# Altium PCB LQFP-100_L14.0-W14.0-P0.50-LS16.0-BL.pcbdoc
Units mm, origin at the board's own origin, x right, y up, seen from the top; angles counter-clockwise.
Board outline 29.4 x 29.73 mm, 2 copper layers (Top Layer, Bottom Layer), stack 0 mm thick; 1 components, 0 nets, 100 pads, 0 vias.
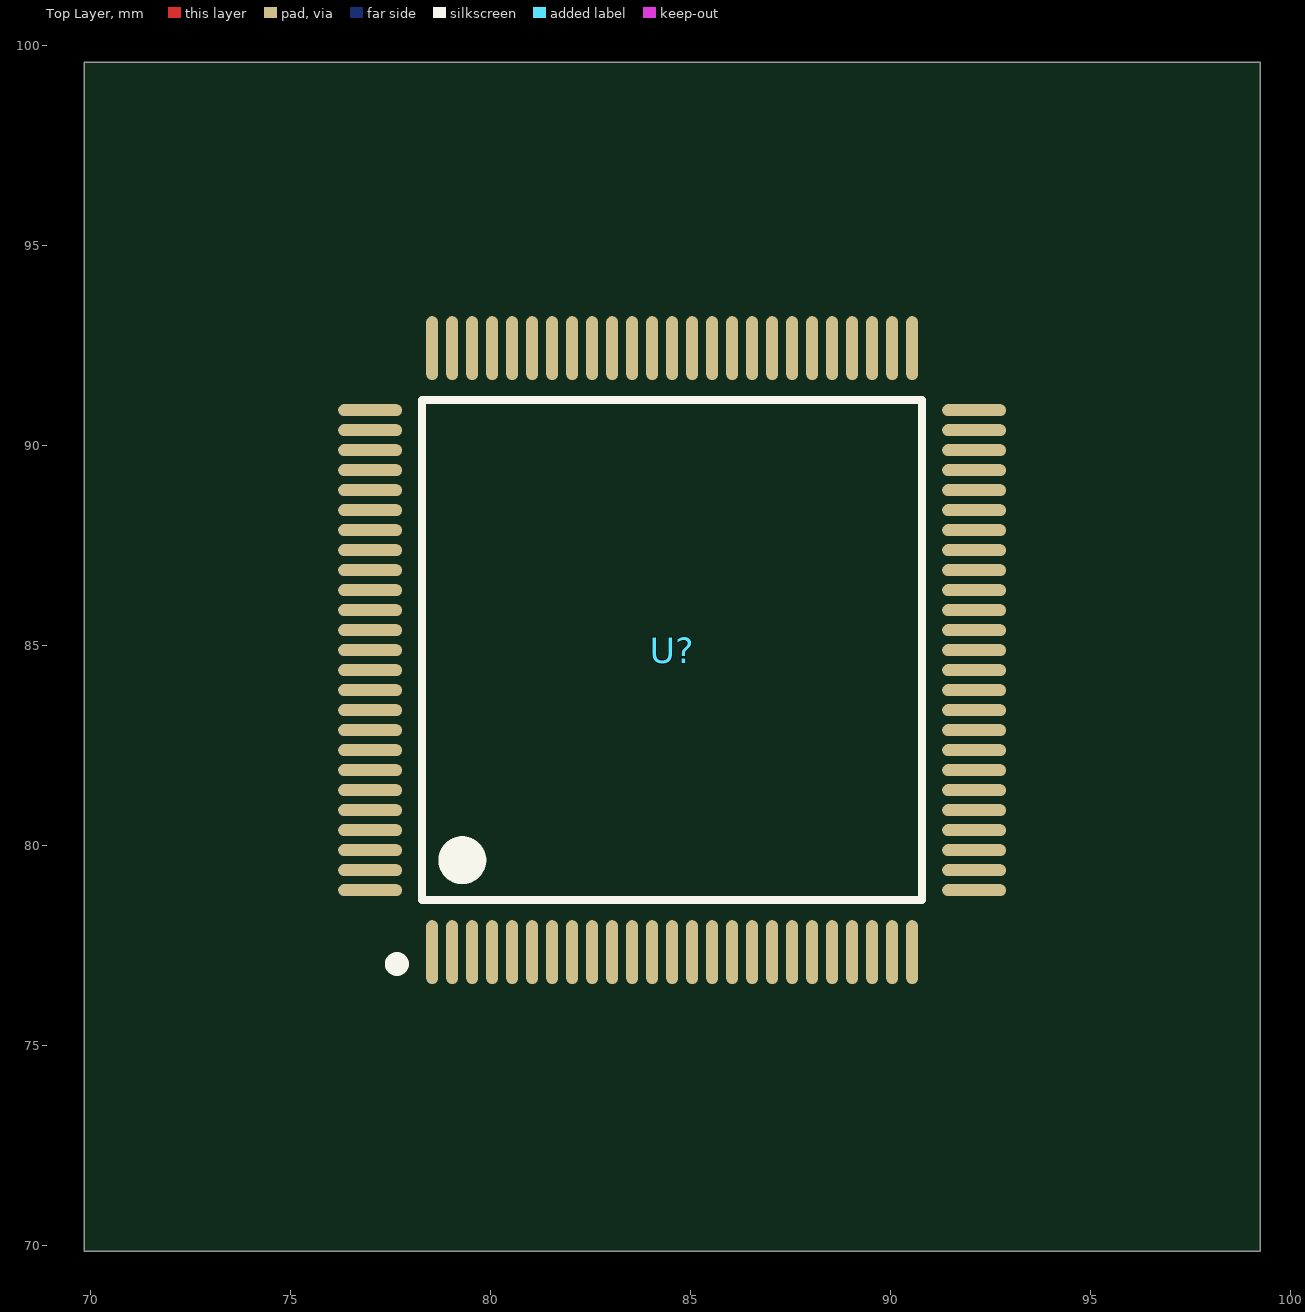
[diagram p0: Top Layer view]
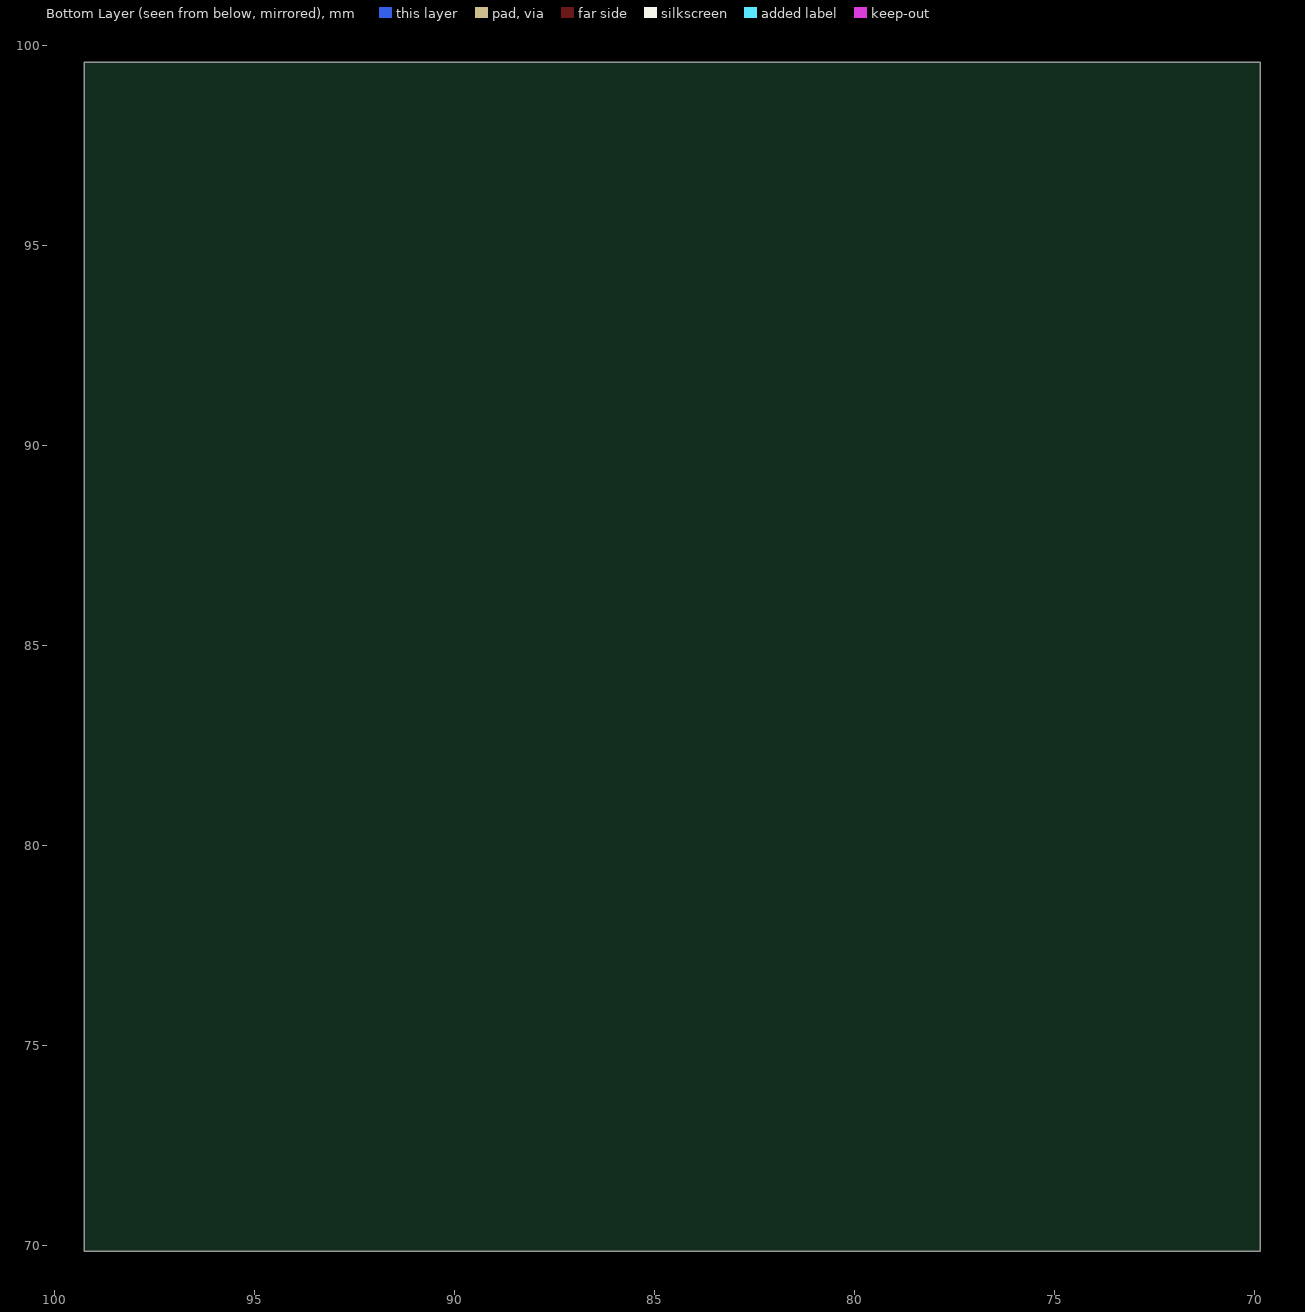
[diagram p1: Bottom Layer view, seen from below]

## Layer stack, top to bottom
Top Layer: signal copper (thickness not stored)
Bottom Layer: signal copper (thickness not stored)

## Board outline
99.25,69.85 69.85,69.85 69.85,99.583 99.25,99.583

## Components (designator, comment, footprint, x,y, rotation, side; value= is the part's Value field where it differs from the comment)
U? "" LQFP-100_L14.0-W14.0-P0.50-LS16.0-BL 84.55,84.883 r0 top

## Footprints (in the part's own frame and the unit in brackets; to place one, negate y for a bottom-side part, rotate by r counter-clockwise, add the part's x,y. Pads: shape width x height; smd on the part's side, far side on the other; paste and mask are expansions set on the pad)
LQFP-100_L14.0-W14.0-P0.50-LS16.0-BL [mm]
  oval 0.3x1.6 smd: 1(-6,-7.55) 2(-5.5,-7.55) 3(-5,-7.55) 4(-4.5,-7.55) 5(-4,-7.55) 6(-3.5,-7.55) 7(-3,-7.55) 8(-2.5,-7.55) 9(-2,-7.55) 10(-1.5,-7.55) 11(-1,-7.55) 12(-0.5,-7.55) 13(0,-7.55) 14(0.5,-7.55) 15(1,-7.55) 16(1.5,-7.55) 17(2,-7.55) 18(2.5,-7.55) 19(3,-7.55) 20(3.5,-7.55) 21(4,-7.55) 22(4.5,-7.55) 23(5,-7.55) 24(5.5,-7.55) 25(6,-7.55) 51(6,7.55) 52(5.5,7.55) 53(5,7.55) 54(4.5,7.55) 55(4,7.55) 56(3.5,7.55) 57(3,7.55) 58(2.5,7.55) 59(2,7.55) 60(1.5,7.55) 61(1,7.55) 62(0.5,7.55) 63(0,7.55) 64(-0.5,7.55) 65(-1,7.55) 66(-1.5,7.55) 67(-2,7.55) 68(-2.5,7.55) 69(-3,7.55) 70(-3.5,7.55) 71(-4,7.55) 72(-4.5,7.55) 73(-5,7.55) 74(-5.5,7.55) 75(-6,7.55)
  oval 1.6x0.3 smd: 26(7.55,-6) 27(7.55,-5.5) 28(7.55,-5) 29(7.55,-4.5) 30(7.55,-4) 31(7.55,-3.5) 32(7.55,-3) 33(7.55,-2.5) 34(7.55,-2) 35(7.55,-1.5) 36(7.55,-1) 37(7.55,-0.5) 38(7.55,0) 39(7.55,0.5) 40(7.55,1) 41(7.55,1.5) 42(7.55,2) 43(7.55,2.5) 44(7.55,3) 45(7.55,3.5) 46(7.55,4) 47(7.55,4.5) 48(7.55,5) 49(7.55,5.5) 50(7.55,6) 76(-7.55,6) 77(-7.55,5.5) 78(-7.55,5) 79(-7.55,4.5) 80(-7.55,4) 81(-7.55,3.5) 82(-7.55,3) 83(-7.55,2.5) 84(-7.55,2) 85(-7.55,1.5) 86(-7.55,1) 87(-7.55,0.5) 88(-7.55,0) 89(-7.55,-0.5) 90(-7.55,-1) 91(-7.55,-1.5) 92(-7.55,-2) 93(-7.55,-2.5) 94(-7.55,-3) 95(-7.55,-3.5) 96(-7.55,-4) 97(-7.55,-4.5) 98(-7.55,-5) 99(-7.55,-5.5) 100(-7.55,-6)
  silkscreen extent -7.03,-8 6.25,6.25

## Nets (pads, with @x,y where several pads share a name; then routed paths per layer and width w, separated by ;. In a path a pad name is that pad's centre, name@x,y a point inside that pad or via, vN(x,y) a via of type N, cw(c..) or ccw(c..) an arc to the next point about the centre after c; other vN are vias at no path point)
pads on no net: U?.1 U?.2 U?.3 U?.4 U?.5 U?.6 U?.7 U?.8 U?.9 U?.10 U?.11 U?.12 U?.13 U?.14 U?.15 U?.16 U?.17 U?.18 U?.19 U?.20 U?.21 U?.22 U?.23 U?.24 U?.25 U?.26 U?.27 U?.28 U?.29 U?.30 U?.31 U?.32 U?.33 U?.34 U?.35 U?.36 U?.37 U?.38 U?.39 U?.40 U?.41 U?.42 U?.43 U?.44 U?.45 U?.46 U?.47 U?.48 U?.49 U?.50 U?.51 U?.52 U?.53 U?.54 U?.55 U?.56 U?.57 U?.58 U?.59 U?.60 U?.61 U?.62 U?.63 U?.64 U?.65 U?.66 U?.67 U?.68 U?.69 U?.70 U?.71 U?.72 U?.73 U?.74 U?.75 U?.76 U?.77 U?.78 U?.79 U?.80 U?.81 U?.82 U?.83 U?.84 U?.85 U?.86 U?.87 U?.88 U?.89 U?.90 U?.91 U?.92 U?.93 U?.94 U?.95 U?.96 U?.97 U?.98 U?.99 U?.100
